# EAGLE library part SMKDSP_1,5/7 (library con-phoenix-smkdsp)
Printklemme, Nennstrom: 17,5 A, Bemessungsspannung: 250 V, Raster: 5,0 mm Source: http://eshop.phoenixcontact.de .. 1733415.pdf
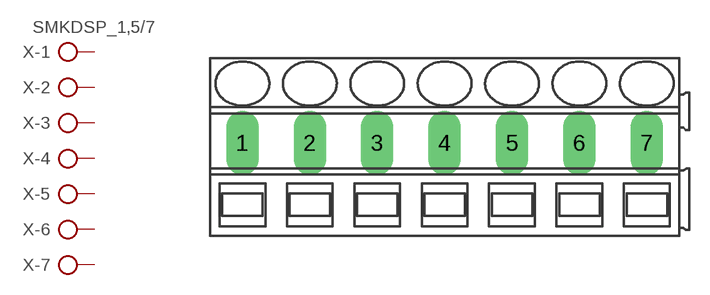
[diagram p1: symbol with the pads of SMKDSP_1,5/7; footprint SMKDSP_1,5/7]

Designator prefix X; gates -1=KLV -2=KL -3=KL -4=KL -5=KL -6=KL -7=KL

## SMKDSP_1,5/7 (OC_FARNELL: unknown; OC_NEWARK: unknown)  [SMKDSP_1,5/7]
1  -1:KL  pas
2  -2:KL  pas
3  -3:KL  pas
4  -4:KL  pas
5  -5:KL  pas
6  -6:KL  pas
7  -7:KL  pas

## Footprint SMKDSP_1,5/7 (pad centres in mm)
Printklemme, Nennstrom: 17,5 A, Bemessungsspannung: 250 V, Raster: 5,0 mm Source: http://eshop.phoenixcontact.de .. 1733415.pdf
drill 1.6 pad 1.8 long: 1 -2.5,0; 2 2.5,0; 3 7.5,0; 4 12.5,0; 5 17.5,0; 6 22.5,0; 7 27.5,0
